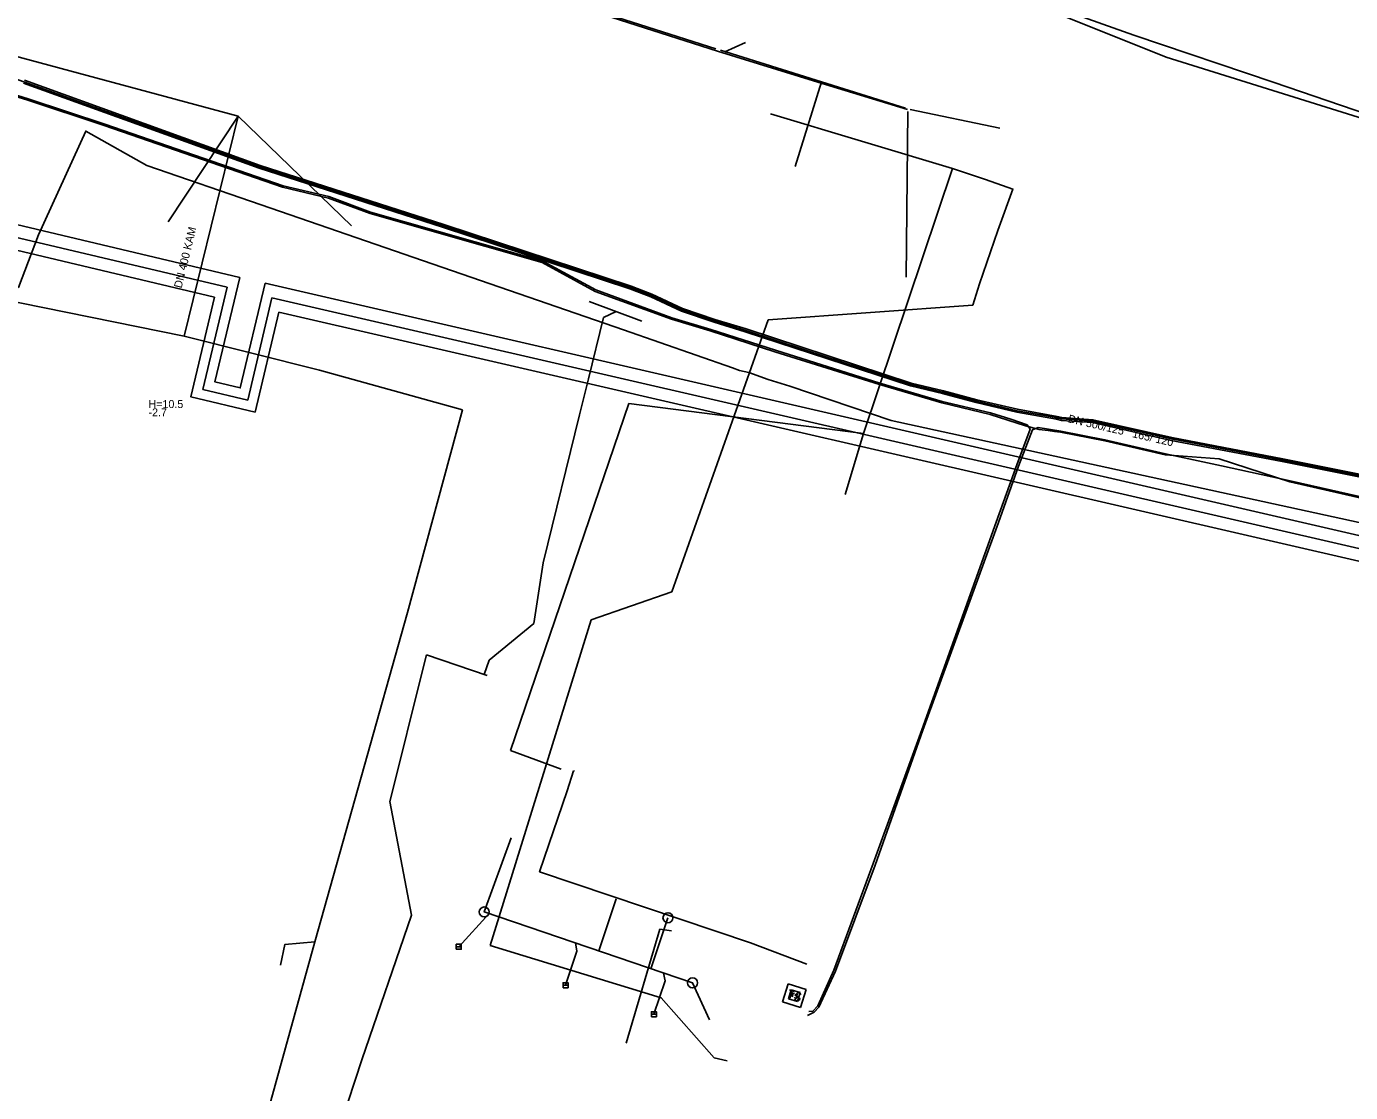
# Model space of a CAD drawing. Extents: x -596024 to -594475, y -1163820 to -1161957.
# Drawn here: x -595307.3 to -595174.9, y -1162163.6 to -1162057 of the extents above; entities that cross this region are included whole.
import ezdxf

# ---------------------------------------------------------------- set-up
doc = ezdxf.new("R2010")
doc.units = 0
for name, color, linetype in [('25', 7, 'Continuous'), ('Level 1', 7, 'Continuous'), ('Vrstva 1', 7, 'Continuous'), ('Vrstva 12', 7, 'Continuous'), ('Vrstva 19', 7, 'Continuous'), ('Vrstva 29', 7, 'Continuous'), ('Vrstva 3', 7, 'Continuous'), ('Vrstva 30', 7, 'Continuous'), ('Vrstva 32', 7, 'Continuous'), ('Vrstva 42', 7, 'Continuous'), ('Vrstva 43', 7, 'Continuous'), ('Vrstva 44', 7, 'Continuous'), ('Vrstva 45', 7, 'Continuous'), ('Vrstva 5', 7, 'Continuous'), ('Vrstva 55', 7, 'Continuous'), ('Vrstva 58', 7, 'Continuous'), ('Vrstva 9', 7, 'Continuous')]:
    doc.layers.add(name, color=color, linetype=linetype)

# ---------------------------------------------------------------- blocks, each defined once
blk = doc.blocks.new('NN640')
at = {"layer": '25'}
for points in [[(-1.89, 1.889), (1.889, 1.889)], [(-1.89, -1.89), (-1.89, 1.889)], [(-1.26, 0.787), (-0.221, 0.787)], [(-0.725, 0.787), (-0.725, -0.788)], [(1.197, 0.661), (0.945, 0.787), (0.661, 0.787), (0.409, 0.661), (0.283, 0.472), (0.283, 0.409), (0.409, 0.22), (1.133, -0.158), (1.259, -0.316), (1.259, -0.473), (1.133, -0.662), (0.913, -0.788), (0.629, -0.788), (0.503, -0.725), (0.283, -0.599)], [(1.889, 1.889), (1.889, -1.89)], [(1.889, -1.89), (-1.89, -1.89)]]:
    blk.add_lwpolyline(points, dxfattribs=at)
blk = doc.blocks.new('VN640')
at = {"layer": '25'}
for points in [[(-1.89, 1.889), (1.889, 1.889)], [(-1.89, -1.89), (-1.89, 1.889)], [(-1.26, 0.787), (-0.221, 0.787)], [(-0.725, 0.787), (-0.725, -0.788)], [(1.197, 0.661), (0.945, 0.787), (0.661, 0.787), (0.409, 0.661), (0.283, 0.472), (0.283, 0.409), (0.409, 0.22), (1.133, -0.158), (1.259, -0.316), (1.259, -0.473), (1.133, -0.662), (0.913, -0.788), (0.629, -0.788), (0.503, -0.725), (0.283, -0.599)], [(1.889, 1.889), (1.889, -1.89)], [(1.889, -1.89), (-1.89, -1.89)]]:
    blk.add_lwpolyline(points, dxfattribs=at)

msp = doc.modelspace()

# ---------------------------------------------------------------- linework, layer by layer
at = {"layer": 'Level 1'}
for points in [[(-595238.38, -1162059.24), (-595252.07, -1162054.87)], [(-595237.49, -1162059.53), (-595235.41, -1162058.62)], [(-595219.42, -1162065.19), (-595237.92, -1162059.39)], [(-595230.46, -1162071.01), (-595227.81, -1162062.56)], [(-595219.35, -1162082.07), (-595219.18, -1162065.51)], [(-595218.94, -1162065.31), (-595209.98, -1162067.18)]]:
    msp.add_lwpolyline(points, dxfattribs=at)
at = {"layer": 'Vrstva 1'}
for p, q in [((-595238.201, -1162059.489), (-595290.626, -1162042.647)), ((-595310.809, -1162059.329), (-595286.125, -1162065.993)), ((-595293.129, -1162076.533), (-595286.125, -1162065.993)), ((-595274.79, -1162076.94), (-595286.125, -1162065.993)), ((-595211.405, -1162072.325), (-595214.712, -1162071.222)), ((-595212.018, -1162082.736), (-595210.18, -1162077.408)), ((-595339.566, -1162078.235), (-595291.516, -1162087.985)), ((-595212.691, -1162084.88), (-595212.018, -1162082.736)), ((-595233.147, -1162086.349), (-595212.691, -1162084.88)), ((-595242.762, -1162113.542), (-595233.147, -1162086.349)), ((-595277.991, -1162091.39), (-595291.516, -1162087.985)), ((-595263.681, -1162095.347), (-595277.991, -1162091.39)), ((-595269.196, -1162115.601), (-595263.681, -1162095.347)), ((-595250.846, -1162116.359), (-595242.762, -1162113.542)), ((-595278.458, -1162148.546), (-595269.196, -1162115.601)), ((-595260.939, -1162148.9), (-595250.846, -1162116.359)), ((-595250.072, -1162149.459), (-595248.33, -1162144.239)), ((-595261.044, -1162145.722), (-595264.07, -1162149.04)), ((-595244.858, -1162151.234), (-595243.158, -1162146.141)), ((-595285.847, -1162175.293), (-595278.458, -1162148.546)), ((-595243.833, -1162154.163), (-595260.939, -1162148.9)), ((-595252.256, -1162149.492), (-595252.412, -1162148.662)), ((-595252.256, -1162149.492), (-595253.39, -1162152.89)), ((-595243.449, -1162152.432), (-595244.57, -1162155.79)), ((-595243.449, -1162152.432), (-595243.593, -1162151.665))]:
    msp.add_line(p, q, dxfattribs=at)
for points in [[(-595219.216, -1162065.307), (-595228.186, -1162062.587), (-595238.201, -1162059.489)], [(-595210.18, -1162077.408), (-595208.676, -1162073.262), (-595211.405, -1162072.325)], [(-595239.006, -1162156.351), (-595240.7, -1162152.65), (-595261.52, -1162145.56), (-595258.826, -1162138.153)], [(-595247.336, -1162158.696), (-595243.967, -1162147.289), (-595242.819, -1162147.443)], [(-595281.88, -1162150.886), (-595281.466, -1162148.815), (-595278.458, -1162148.546)], [(-595237.231, -1162160.457), (-595238.532, -1162160.151), (-595243.833, -1162154.163)]]:
    msp.add_lwpolyline(points, dxfattribs=at)
at = {"layer": 'Vrstva 12'}
for p, q in [((-595251.027, -1162084.516), (-595245.778, -1162086.465)), ((-595249.61, -1162086.12), (-595248.351, -1162085.51)), ((-595251.994, -1162095.841), (-595255.622, -1162110.63)), ((-595255.622, -1162110.63), (-595256.561, -1162116.7)), ((-595256.561, -1162116.7), (-595261.02, -1162120.38)), ((-595267.301, -1162119.85), (-595261.221, -1162121.93)), ((-595261.02, -1162120.38), (-595261.516, -1162121.829)), ((-595270.961, -1162134.53), (-595269.703, -1162129.486)), ((-595268.78, -1162145.87), (-595270.961, -1162134.53)), ((-595268.78, -1162145.87), (-595273.771, -1162160.34))]:
    msp.add_line(p, q, dxfattribs=at)
for points in [[(-595249.61, -1162086.12), (-595251.115, -1162092.255), (-595251.994, -1162095.841)], [(-595269.703, -1162129.486), (-595268.789, -1162125.822), (-595267.301, -1162119.85)], [(-595273.771, -1162160.34), (-595282.791, -1162187.895), (-595284.015, -1162191.634)]]:
    msp.add_lwpolyline(points, dxfattribs=at)
at = {"layer": 'Vrstva 19'}
for points in [[(-595342.59, -1162075.96), (-595328.67, -1162078.56), (-595308.09, -1162083.1), (-595306.06, -1162077.84), (-595301.36, -1162067.47), (-595295.24, -1162070.91), (-595283.81, -1162074.83), (-595247.59, -1162087.34), (-595236.71, -1162091.13)], [(-595236.71, -1162091.13), (-595236.02, -1162091.41), (-595235.06, -1162091.61), (-595233.13, -1162092.3), (-595230.98, -1162092.97)], [(-595230.98, -1162092.97), (-595220.85, -1162096.4), (-595168.86, -1162107.75), (-595081.2, -1162125.02), (-594997.53, -1162134.17), (-594961.69, -1162138.72), (-594953.62, -1162140.15), (-594950.84, -1162140.46)]]:
    msp.add_lwpolyline(points, dxfattribs=at)
at = {"layer": 'Vrstva 29'}
for p, q in [((-595287.226, -1162083.088), (-595352.843, -1162067.579)), ((-595152.763, -1162114.138), (-595282.746, -1162084.134))]:
    msp.add_line(p, q, dxfattribs=at)
msp.add_lwpolyline([(-595282.746, -1162084.134), (-595285.164, -1162094.364), (-595289.641, -1162093.305), (-595287.226, -1162083.088)], dxfattribs=at)
at = {"layer": 'Vrstva 3'}
for p, q in [((-595264.32, -1162149.04), (-595263.82, -1162149.04)), ((-595253.64, -1162152.89), (-595253.14, -1162152.89)), ((-595244.82, -1162155.79), (-595244.32, -1162155.79))]:
    msp.add_line(p, q, dxfattribs=at)
for points in [[(-595264.32, -1162149.29), (-595263.82, -1162149.29), (-595263.82, -1162148.79), (-595264.32, -1162148.79)], [(-595253.64, -1162153.14), (-595253.14, -1162153.14), (-595253.14, -1162152.64), (-595253.64, -1162152.64)], [(-595244.82, -1162156.04), (-595244.32, -1162156.04), (-595244.32, -1162155.54), (-595244.82, -1162155.54)]]:
    msp.add_lwpolyline(points, close=True, dxfattribs=at)
for centre in [(-595261.52, -1162145.56), (-595243.158, -1162146.141), (-595240.7, -1162152.65)]:
    msp.add_circle(centre, 0.5, dxfattribs=at)
at = {"layer": 'Vrstva 30'}
for p, q in [((-595285.966, -1162082.102), (-595352.555, -1162066.363)), ((-595288.486, -1162084.074), (-595353.131, -1162068.795)), ((-595151.514, -1162113.143), (-595283.433, -1162082.693)), ((-595154.013, -1162115.132), (-595282.06, -1162085.575))]:
    msp.add_line(p, q, dxfattribs=at)
for points in [[(-595283.433, -1162082.693), (-595285.907, -1162093.161), (-595288.438, -1162092.562), (-595285.966, -1162082.102)], [(-595282.06, -1162085.575), (-595284.421, -1162095.567), (-595290.844, -1162094.048), (-595288.486, -1162084.074)]]:
    msp.add_lwpolyline(points, dxfattribs=at)
at = {"layer": 'Vrstva 42'}
msp.add_line((-595252.512, -1162131.473), (-595252.61, -1162131.44), dxfattribs=at)
for points in [[(-595265.62, -1162076.94), (-595283.96, -1162071.04), (-595307.534, -1162062.531), (-595330.81, -1162054.13), (-595340.24, -1162051.31), (-595347.11, -1162048.66), (-595353.84, -1162046.06), (-595366.2, -1162040.37), (-595369.17, -1162039.23), (-595376.99, -1162037.1), (-595381.84, -1162035.47), (-595388.2, -1162032.14), (-595404.75, -1162022.97), (-595411.98, -1162016.9), (-595423.09, -1162006.33), (-595431.77, -1161997.05), (-595439.77, -1161989.85), (-595447.39, -1161983.57), (-595456.24, -1161976.23), (-595467.51, -1161967.55), (-595477.92, -1161956.88)], [(-595123.252, -1162070.9), (-595127.046, -1162075.087), (-595131.425, -1162077.351), (-595133.774, -1162077.945), (-595134.89, -1162077.91), (-595136.65, -1162077.604), (-595147.355, -1162074.403), (-595157.547, -1162070.979), (-595170.572, -1162066.726), (-595182.551, -1162062.626), (-595196.604, -1162057.892), (-595208.884, -1162053.49), (-595222.737, -1162048.209)], [(-595123.252, -1162070.9), (-595127.046, -1162075.087), (-595131.425, -1162077.351), (-595133.774, -1162077.945), (-595134.89, -1162077.91), (-595136.65, -1162077.604), (-595147.355, -1162074.403), (-595157.547, -1162070.979), (-595170.572, -1162066.726), (-595182.551, -1162062.626), (-595196.604, -1162057.892), (-595208.884, -1162053.49), (-595222.737, -1162048.209)], [(-595307.585, -1162062.672), (-595284.008, -1162071.182), (-595265.68, -1162077.078), (-595246.954, -1162083.25), (-595244.859, -1162084.062), (-595241.806, -1162085.48), (-595238.556, -1162086.583), (-595235.426, -1162087.543), (-595218.93, -1162092.955), (-595215.707, -1162093.726), (-595212.346, -1162094.625), (-595208.289, -1162095.577), (-595204.331, -1162096.293), (-595203.819, -1162096.399), (-595200.732, -1162096.629), (-595192.871, -1162098.397), (-595181.769, -1162100.527), (-595172.443, -1162102.396)], [(-595307.483, -1162062.39), (-595283.912, -1162070.898), (-595265.56, -1162076.801), (-595246.846, -1162082.97), (-595244.761, -1162083.778), (-595241.694, -1162085.2), (-595238.464, -1162086.297), (-595235.334, -1162087.257), (-595218.85, -1162092.665), (-595215.633, -1162093.434), (-595212.274, -1162094.334), (-595208.231, -1162095.283), (-595204.257, -1162096.003), (-595203.781, -1162096.101), (-595200.688, -1162096.331), (-595192.809, -1162098.103), (-595181.711, -1162100.233), (-595172.377, -1162102.104), (-595161.485, -1162104.834)], [(-595265.62, -1162076.94), (-595246.9, -1162083.11), (-595244.81, -1162083.92), (-595241.75, -1162085.34), (-595238.51, -1162086.44), (-595235.38, -1162087.4), (-595229.41, -1162089.37), (-595224.01, -1162091.15), (-595218.89, -1162092.81), (-595215.67, -1162093.58), (-595212.31, -1162094.48), (-595208.26, -1162095.43), (-595204.74, -1162096.05), (-595204.294, -1162096.148)], [(-595039.58, -1162125.26), (-595050.24, -1162124.34), (-595062.15, -1162123.71), (-595072.56, -1162122.57), (-595081.91, -1162121.18), (-595089.02, -1162119.82), (-595099, -1162117.72), (-595108.42, -1162115.26), (-595114.75, -1162114), (-595131.993, -1162110.84), (-595144.3, -1162108.54), (-595154.08, -1162106.64), (-595161.52, -1162104.98), (-595172.41, -1162102.25), (-595181.74, -1162100.38), (-595192.84, -1162098.25), (-595200.71, -1162096.48), (-595203.8, -1162096.25), (-595204.294, -1162096.148)], [(-595252.61, -1162131.44), (-595253.23, -1162133.46), (-595255.99, -1162141.54), (-595234.92, -1162148.65), (-595229.287, -1162150.795)]]:
    msp.add_lwpolyline(points, dxfattribs=at)
at = {"layer": 'Vrstva 44'}
for points in [[(-595322.187, -1162058.882), (-595315.82, -1162061.54), (-595307.11, -1162064.24), (-595299.46, -1162066.77), (-595281.63, -1162072.93), (-595277.06, -1162074.02), (-595272.89, -1162075.57), (-595255.67, -1162080.48), (-595250.38, -1162083.36), (-595242.77, -1162086.14), (-595238.88, -1162087.31), (-595232.42, -1162089.39), (-595221.97, -1162092.68), (-595215.76, -1162094.51), (-595210.91, -1162095.65), (-595208.888, -1162096.279)], [(-595229.217, -1162155.908), (-595228.533, -1162155.584), (-595228.081, -1162155.068), (-595226.427, -1162151.478), (-595222.442, -1162140.868), (-595217.693, -1162127.381), (-595210.125, -1162106.626), (-595208.117, -1162100.965), (-595206.706, -1162097.336), (-595206.15, -1162097.114), (-595203.891, -1162097.478)], [(-595208.888, -1162096.279), (-595207.27, -1162096.853), (-595206.944, -1162097.274), (-595208.277, -1162100.836), (-595210.368, -1162106.587), (-595217.78, -1162127.359), (-595222.636, -1162140.725), (-595226.573, -1162151.366), (-595228.189, -1162154.947), (-595228.68, -1162155.472), (-595229.074, -1162155.505)], [(-595203.891, -1162097.478), (-595199.48, -1162098.33), (-595193.44, -1162099.75), (-595187.841, -1162100.948), (-595180.98, -1162102.45), (-595171.96, -1162104.49)]]:
    msp.add_lwpolyline(points, dxfattribs=at)
at = {"layer": 'Vrstva 5'}
for p, q in [((-595223.618, -1162097.704), (-595214.712, -1162071.222)), ((-595258.905, -1162129.402), (-595247.063, -1162094.713)), ((-595247.063, -1162094.713), (-595223.618, -1162097.704)), ((-595225.441, -1162103.807), (-595223.618, -1162097.704)), ((-595253.843, -1162131.29), (-595258.905, -1162129.402))]:
    msp.add_line(p, q, dxfattribs=at)
at = {"layer": 'Vrstva 55'}
msp.add_lwpolyline([(-595321.775, -1162013.487), (-595318.23, -1162016.77), (-595317.242, -1162017.196), (-595300.264, -1162024.515), (-595266.45, -1162034.939), (-595235.864, -1162045.47), (-595212.1, -1162052.55), (-595193.372, -1162060.075), (-595157.64, -1162071.23), (-595161.463, -1162085.686), (-595139.397, -1162093.253), (-595129.66, -1162095), (-595122.94, -1162095.264), (-595113.539, -1162091.897)], dxfattribs=at)
at = {"layer": 'Vrstva 58'}
msp.add_lwpolyline([(-595315.872, -1162061.685), (-595307.157, -1162064.386), (-595299.509, -1162066.915), (-595281.673, -1162073.078), (-595277.105, -1162074.167), (-595272.938, -1162075.716), (-595255.728, -1162080.623), (-595250.443, -1162083.5), (-595242.819, -1162086.286), (-595238.926, -1162087.457), (-595232.467, -1162089.536), (-595222.015, -1162092.827), (-595215.799, -1162094.659), (-595210.95, -1162095.798), (-595207.425, -1162096.957), (-595206.049, -1162097.296), (-595205.156, -1162097.426), (-595204.537, -1162097.521), (-595203.912, -1162097.588), (-595199.504, -1162098.44), (-595193.457, -1162099.861), (-595188.052, -1162100.251), (-595181.01, -1162102.558), (-595171.983, -1162104.6)], dxfattribs=at)
at = {"layer": 'Vrstva 9'}
for p, q in [((-595291.516, -1162087.985), (-595286.125, -1162065.993)), ((-595214.712, -1162071.222), (-595232.894, -1162065.746))]:
    msp.add_line(p, q, dxfattribs=at)

# ---------------------------------------------------------------- block references
at = {"layer": 'Vrstva 43', "xscale": 0.49999999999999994, "yscale": 0.5000000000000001, "rotation": -18.000000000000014}
msp.add_blockref('NN640', (-595230.527, -1162153.929), dxfattribs=at)
at = {"layer": 'Vrstva 45', "xscale": 0.24999999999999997, "yscale": 0.25000000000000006, "rotation": -18.000000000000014}
msp.add_blockref('VN640', (-595230.527, -1162153.929), dxfattribs=at)

# ---------------------------------------------------------------- texts
at = {"layer": 'Vrstva 12'}
msp.add_text('DN 400 KAM', height=0.8, rotation=76.22683, dxfattribs=at).set_placement((-595291.776, -1162083.229))
at = {"layer": 'Vrstva 32'}
for s, p in [('H=10.5  ', (-595295.083, -1162095.167)), ('-2.7', (-595295.083, -1162095.999))]:
    msp.add_text(s, height=0.8, dxfattribs=at).set_placement(p)
msp.add_text('DN 500/125   165/ 120', height=0.8, rotation=346.98325, dxfattribs=at).set_placement((-595203.227, -1162096.585))

doc.saveas('drawing.dxf')
